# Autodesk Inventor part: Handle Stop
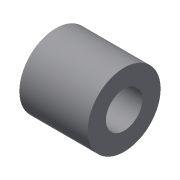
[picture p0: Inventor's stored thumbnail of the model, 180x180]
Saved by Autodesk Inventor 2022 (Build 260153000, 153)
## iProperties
Created: 2002-02
Part Number: Handle Stop
Document SubType Name: Modeling
Designer: ***
Density: 1 g/cm^3
Material: Generic
Mass: 2.36248 g
Surface Area: 14.8283 cm^2
Volume: 2.36248 cm^3
Appearance: Default
Control State: 0
Master: False
Checked Out: False
Shininess: 77.0
Length Units: 11269
Angle Units: 11279
Time Units: 11290
Mass Units: 11283
Length Display Precision: 3
Angle Display Precision: 2
Compacted: True
Density: 0.0
Volumn: 0.0
Area: 0.0
PropertySet Name: Model Information
Author: ***
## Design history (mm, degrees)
sketch "Sketch1"
  geometry: L1 (0, 0)-(0, -2); L2 (0, -2)-(8, -2); L3 (8, -2)-(8, 13); L4 (8, 13)-(4, 13); L5 (4, 13)-(4, 0); L6 (4, 0)-(0, 0)
  constraints: 12 end point, 4 parallel, 1 perpendicular, 1 vertical
  dimensions: "d0" = 16 diameter of L3 L1; "d1" = 8 diameter of L5 L1; "d2" = 2 distance of L1.start L1.end; "d3" = 15 distance of L2.end L3.end
revolve "Revolution1" sketch "Sketch1" stored, may be unused: angle "d4" = 90 deg
body "Solid1"
